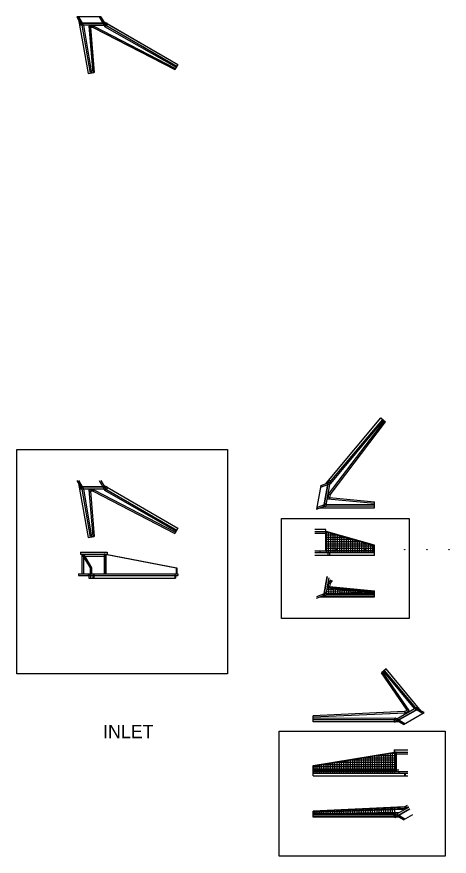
# Model space of a CAD drawing. Extents: x -21 to 491, y -228 to 155.
# Drawn here: x 295.5 to 490.7, y -228.4 to 150.5 of the extents above; entities that cross this region are included whole.
import ezdxf

# ---------------------------------------------------------------- set-up
doc = ezdxf.new("R2010")
doc.units = 0
for name, color, linetype in [('1', 7, 'Continuous'), ('4', 7, 'Continuous'), ('B-Gen-Construction Line', 7, 'Continuous'), ('B-Gen-Hidden', 7, 'Continuous'), ('B-Gen-Object', 7, 'Continuous'), ('B-Gen-Rebar', 7, 'Continuous')]:
    doc.layers.add(name, color=color, linetype=linetype)

msp = doc.modelspace()

# ---------------------------------------------------------------- linework, layer by layer
at = {"layer": '4'}
msp.add_line((429.19, -189.4), (467.92, -189.4), dxfattribs=at)
for points in [[(295.48, -44.74), (390.59, -44.74), (390.59, -146.09), (295.48, -146.09)], [(415, -75.9), (472.51, -75.9), (472.51, -121.1), (415, -121.1)], [(413.88, -171.92), (488.79, -171.92), (488.79, -228.35), (413.88, -228.35)]]:
    msp.add_lwpolyline(points, close=True, dxfattribs=at)
at = {"layer": 'B-Gen-Construction Line'}
for points in [[(323.39, 149.19), (327.69, 124.82), (330.4, 125.3), (328.75, 145.66), (328.75, 146.66), (324.85, 146.66)], [(334.63, 148.39), (368.17, 129.03), (366.8, 126.64), (330.03, 145.66), (330.03, 146.66), (335.63, 146.66)], [(328.75, 146.66), (330.03, 146.66), (330.03, 145.66), (328.75, 145.66)]]:
    msp.add_lwpolyline(points, close=True, dxfattribs=at)
at = {"layer": 'B-Gen-Hidden'}
for p, q in [((323.41, 150.49), (325.49, 146.89)), ((332.65, 150.49), (334.86, 146.66)), ((324.28, 147.66), (324.85, 146.66)), ((325.53, 146.66), (325.49, 146.89)), ((330.19, 146.33), (328.03, 146.33)), ((328.03, 146.33), (329.74, 125.18)), ((328.75, 145.66), (328.09, 145.61)), ((330.03, 145.66), (330.19, 146.33)), ((330.19, 146.33), (367.13, 127.22)), ((335.05, 147.66), (335.63, 146.66)), ((335.9, 147.66), (336.21, 147.48)), ((436.23, -64.98), (461.46, -31.91)), ((323.41, -58.82), (325.49, -62.42)), ((332.65, -58.82), (334.86, -62.65)), ((432.56, -61.83), (436.72, -60.32)), ((435.77, -59.96), (436.85, -59.56)), ((435.91, -59.12), (436.15, -58.85)), ((324.28, -61.65), (324.85, -62.65)), ((325.53, -62.65), (325.49, -62.42)), ((330.19, -62.99), (328.03, -62.99)), ((328.03, -62.99), (329.74, -84.13)), ((328.75, -63.65), (328.09, -63.71)), ((330.03, -63.65), (330.19, -62.99)), ((330.19, -62.99), (367.13, -82.09)), ((335.05, -61.65), (335.63, -62.65)), ((335.9, -61.65), (336.21, -61.83)), ((436.23, -64.98), (435.86, -67.1)), ((435.86, -67.1), (456.98, -69.09)), ((436.86, -65.25), (436.23, -64.98)), ((436.64, -66.51), (436.58, -67.17)), ((430.96, -70.93), (434.86, -69.51)), ((433.89, -70.57), (434.98, -70.18)), ((435.1, -69.51), (434.86, -69.51)), ((434.98, -82.71), (429.94, -82.71)), ((434.86, -81.92), (434.86, -90.71)), ((432.23, -90.71), (429.94, -90.71)), ((324.85, -92.09), (335.85, -92.09)), ((325.53, -92.05), (325.53, -100.88)), ((325.53, -92.88), (326.02, -92.88)), ((335.63, -92.05), (335.63, -100.88)), ((436.64, -91.46), (436.64, -92.71)), ((328.03, -100.88), (328.03, -101.63)), ((328.75, -100.88), (328.75, -101.63)), ((328.75, -101.63), (328.75, -102.88)), ((329.74, -101.63), (366.8, -101.63)), ((330.03, -100.88), (330.03, -101.63)), ((330.03, -100.88), (330.03, -102.88)), ((330.19, -100.88), (330.19, -102.88)), ((436.23, -105.12), (435.86, -107.25)), ((436.23, -105.12), (437.42, -103.57)), ((436.86, -105.39), (436.23, -105.12)), ((430.96, -111.07), (434.86, -109.65)), ((435.1, -109.65), (434.86, -109.65)), ((435.86, -107.25), (456.98, -109.24)), ((436.64, -106.65), (436.58, -107.32)), ((433.89, -110.71), (434.98, -110.32)), ((472.6, -162.66), (460.55, -145.2)), ((470.73, -163.74), (472.6, -162.66)), ((471.65, -162.44), (472.19, -162.06)), ((474.94, -161.7), (475.09, -161.88)), ((478.68, -163.95), (475.09, -161.88)), ((476.52, -161.94), (475.52, -161.36)), ((470.73, -163.74), (429.19, -165.67)), ((470.68, -168.57), (466.86, -166.36)), ((470.54, -163.08), (470.73, -163.74)), ((466.46, -167.75), (466.09, -167.75)), ((467.19, -167.33), (466.19, -166.75)), ((465.94, -181.36), (466.19, -181.31)), ((466.19, -181.36), (466.19, -181.31)), ((466.19, -181.31), (466.78, -181.31)), ((466.31, -181.56), (466.31, -181.31)), ((466.31, -181.56), (466.31, -190.15)), ((466.78, -181.56), (466.78, -181.31)), ((466.78, -181.56), (466.78, -190.15)), ((466.19, -182.15), (472, -182.15)), ((467.92, -190.15), (472, -190.15)), ((470.54, -190.94), (470.54, -192.15)), ((470.73, -206.75), (429.19, -208.67)), ((470.54, -206.09), (470.73, -206.75)), ((470.73, -206.75), (472.22, -205.89)), ((466.46, -210.75), (466.09, -210.75)), ((467.19, -210.33), (466.19, -209.75)), ((470.68, -211.58), (466.86, -209.37))]:
    msp.add_line(p, q, dxfattribs=at)
at = {"layer": 'B-Gen-Object'}
for p, q in [((333.42, 150.49), (322.64, 150.49)), ((322.64, 150.49), (324.28, 147.66)), ((323.39, 149.19), (327.69, 124.82)), ((333.42, 150.49), (335.05, 147.66)), ((334.63, 148.39), (335.9, 147.66)), ((336.21, 147.66), (324.27, 147.66)), ((324.27, 146.66), (324.27, 147.66)), ((336.21, 147.49), (324.27, 147.49)), ((336.21, 146.66), (324.27, 146.66)), ((324.85, 146.66), (328.67, 124.99)), ((325.53, 146.66), (324.87, 146.54)), ((325.53, 146.66), (329.17, 125.08)), ((330.03, 145.66), (328.75, 145.66)), ((328.75, 145.66), (330.4, 125.3)), ((330.03, 145.66), (366.8, 126.64)), ((334.86, 146.66), (335.14, 146.17)), ((335.14, 146.17), (367.42, 127.73)), ((335.63, 146.66), (335.3, 146.08)), ((335.63, 146.66), (367.67, 128.16)), ((336.21, 146.66), (336.21, 147.66)), ((336.21, 147.48), (368.17, 129.03)), ((368.17, 129.03), (366.8, 126.64)), ((327.69, 124.82), (330.4, 125.3)), ((436.15, -58.85), (459.87, -30.58)), ((436.85, -59.56), (460.63, -31.22)), ((436.86, -65.25), (461.97, -32.34)), ((437.25, -60.13), (461.02, -31.54)), ((459.87, -30.58), (461.97, -32.34)), ((322.64, -58.82), (324.28, -61.65)), ((323.39, -60.12), (327.69, -84.49)), ((333.42, -58.82), (335.05, -61.65)), ((432.7, -61.07), (435.77, -59.96)), ((435.97, -58.81), (433.89, -70.58)), ((436.13, -58.84), (434.06, -70.6)), ((436.95, -58.99), (434.88, -70.75)), ((434.97, -60.25), (435.91, -59.12)), ((436.95, -58.99), (435.97, -58.81)), ((436.72, -60.32), (437.25, -60.13)), ((436.85, -59.56), (437.36, -59.99)), ((336.21, -61.65), (324.27, -61.65)), ((324.27, -62.65), (324.27, -61.65)), ((336.21, -61.82), (324.27, -61.82)), ((336.21, -62.65), (324.27, -62.65)), ((324.85, -62.65), (328.67, -84.32)), ((325.53, -62.65), (324.87, -62.77)), ((325.53, -62.65), (329.17, -84.23)), ((330.03, -63.65), (328.75, -63.65)), ((328.75, -63.65), (330.4, -84.01)), ((330.03, -63.65), (366.8, -82.67)), ((334.63, -60.92), (335.9, -61.65)), ((334.86, -62.65), (335.14, -63.14)), ((335.14, -63.14), (367.42, -81.59)), ((335.63, -62.65), (335.3, -63.23)), ((335.63, -62.65), (367.67, -81.15)), ((336.21, -62.65), (336.21, -61.65)), ((336.21, -61.83), (368.17, -80.29)), ((432.7, -61.07), (430.83, -71.69)), ((436.86, -65.25), (436.64, -66.51)), ((436.64, -66.51), (456.98, -68.43)), ((430.83, -71.69), (433.89, -70.57)), ((432.23, -71.18), (456.98, -71.18)), ((434.88, -70.75), (433.89, -70.58)), ((434.98, -70.18), (456.98, -70.18)), ((435.1, -69.51), (456.98, -69.68)), ((456.98, -71.18), (456.98, -68.43)), ((368.17, -80.29), (366.8, -82.67)), ((434.98, -80.92), (429.94, -80.92)), ((434.98, -81.92), (429.94, -81.92)), ((434.98, -81.92), (429.94, -81.92)), ((434.98, -90.71), (434.98, -80.92)), ((435.1, -81.88), (434.98, -81.88)), ((456.98, -88.05), (435.1, -81.88)), ((327.69, -84.49), (330.4, -84.01)), ((456.98, -90.71), (432.23, -90.71)), ((432.23, -90.71), (432.23, -91.5)), ((456.98, -92.71), (456.98, -88.05)), ((324.27, -91.09), (336.21, -91.09)), ((324.27, -91.09), (324.27, -92.09)), ((324.27, -92.09), (324.85, -92.09)), ((324.85, -92.05), (325.53, -92.05)), ((324.85, -92.05), (328.67, -98.22)), ((324.85, -92.05), (324.85, -100.88)), ((325.53, -92.05), (329.17, -98.22)), ((326.02, -92.88), (334.86, -92.88)), ((334.86, -92.05), (334.86, -100.88)), ((335.21, -92.05), (334.86, -92.05)), ((335.14, -92.05), (335.14, -100.88)), ((335.21, -92.05), (335.63, -92.05)), ((335.3, -92.05), (367.42, -98.22)), ((335.63, -92.05), (367.67, -98.22)), ((335.85, -92.09), (336.21, -92.09)), ((336.21, -91.09), (336.21, -92.09)), ((432.23, -91.5), (429.94, -91.5)), ((456.98, -92.71), (429.94, -92.71)), ((436.75, -91.46), (432.23, -91.46)), ((435.86, -91.46), (435.86, -92.71)), ((456.98, -91.46), (436.75, -91.46)), ((328.67, -98.22), (329.17, -98.22)), ((328.67, -98.22), (328.67, -100.88)), ((329.17, -98.22), (329.17, -100.88)), ((367.42, -98.22), (367.42, -100.88)), ((367.42, -98.22), (367.67, -98.22)), ((367.67, -98.22), (367.67, -100.88)), ((323.39, -100.88), (323.39, -101.63)), ((323.39, -100.88), (368.17, -100.88)), ((323.39, -101.63), (329.74, -101.63)), ((327.69, -100.88), (327.69, -101.63)), ((328.03, -101.63), (328.03, -102.88)), ((329.74, -101.63), (329.74, -102.88)), ((330.4, -102.88), (330.4, -100.88)), ((366.8, -100.88), (366.8, -102.88)), ((366.8, -101.63), (368.17, -101.63)), ((367.13, -101.63), (367.13, -102.88)), ((368.17, -100.88), (368.17, -101.63)), ((435.42, -102.05), (433.89, -110.72)), ((435.57, -102.16), (434.06, -110.75)), ((328.03, -102.88), (366.8, -102.88)), ((329.74, -102.88), (330.4, -102.88)), ((329.74, -102.88), (330.4, -102.88)), ((366.8, -102.88), (367.13, -102.88)), ((436.32, -102.73), (434.88, -110.89)), ((436.86, -105.39), (436.64, -106.65)), ((436.86, -105.39), (437.95, -103.97)), ((435.1, -109.65), (456.98, -109.82)), ((436.64, -106.65), (456.98, -108.57)), ((456.98, -111.32), (456.98, -108.57)), ((430.83, -111.83), (433.89, -110.71)), ((432.23, -111.32), (456.98, -111.32)), ((434.88, -110.89), (433.89, -110.72)), ((434.98, -110.32), (456.98, -110.32)), ((462.15, -143.86), (460.04, -145.63)), ((478.05, -162.82), (462.15, -143.86)), ((471.65, -162.44), (460.04, -145.63)), ((474.94, -161.7), (461, -144.83)), ((475.52, -161.36), (461.38, -144.51)), ((465.68, -167.04), (476.03, -161.07)), ((466.1, -167.76), (476.44, -161.79)), ((466.18, -167.91), (476.53, -161.93)), ((470.54, -163.08), (471.65, -162.44)), ((476.03, -161.07), (476.53, -161.93)), ((479.35, -163.57), (476.52, -161.94)), ((470.54, -163.08), (429.19, -165)), ((429.19, -167.75), (429.19, -165)), ((466.37, -166.08), (429.19, -166.25)), ((466.19, -166.75), (466.19, -166.08)), ((466.86, -166.36), (466.37, -166.08)), ((470.02, -168.96), (479.35, -163.57)), ((466.19, -166.75), (429.19, -166.75)), ((466.09, -167.75), (429.19, -167.75)), ((465.68, -167.04), (466.18, -167.91)), ((467.92, -167.75), (466.46, -167.75)), ((470.02, -168.96), (467.19, -167.33)), ((429.19, -187.48), (465.94, -181.36)), ((465.74, -180.36), (472, -180.36)), ((465.74, -180.36), (465.74, -181.36)), ((465.74, -181.36), (472, -181.36)), ((466.19, -181.36), (466.19, -190.15)), ((429.19, -192.15), (429.19, -187.48)), ((429.19, -190.15), (467.92, -190.15)), ((429.19, -190.9), (467.92, -190.9)), ((429.19, -192.15), (472, -192.15)), ((467.92, -190.15), (467.92, -190.94)), ((467.92, -190.9), (467.92, -190.9)), ((467.92, -190.94), (472, -190.94)), ((470.73, -190.94), (470.73, -192.15)), ((470.54, -206.09), (429.19, -208)), ((429.19, -210.75), (429.19, -208)), ((465.68, -210.05), (472.39, -206.18)), ((466.1, -210.77), (472.81, -206.9)), ((466.18, -210.91), (472.89, -207.04)), ((470.54, -206.09), (471.89, -205.31)), ((466.37, -209.09), (429.19, -209.25)), ((466.19, -209.75), (429.19, -209.75)), ((466.09, -210.75), (429.19, -210.75)), ((465.68, -210.05), (466.18, -210.91)), ((466.19, -209.75), (466.19, -209.09)), ((466.86, -209.37), (466.37, -209.09)), ((467.92, -210.75), (466.46, -210.75)), ((470.02, -211.96), (467.19, -210.33)), ((470.02, -211.96), (474.3, -209.49))]:
    msp.add_line(p, q, dxfattribs=at)
for centre, radius in [((439.73, -89.96), 0.0834), ((452.73, -89.96), 0.0834), ((470.58, -89.96), 0.0834), ((480.58, -89.96), 0.0834), ((490.58, -89.96), 0.0834), ((437.44, -189.4), 0.0833), ((447.44, -189.4), 0.0833), ((457.44, -189.4), 0.0833)]:
    msp.add_circle(centre, radius, dxfattribs=at)
at = {"layer": 'B-Gen-Rebar'}
for p, q in [((456.81, -88.26), (435.15, -82.15)), ((436.55, -82.46), (435.15, -82.46)), ((435.23, -91.3), (435.23, -82.14)), ((436.23, -91.3), (436.23, -82.37)), ((437.23, -91.3), (437.23, -82.65)), ((438.23, -91.3), (438.23, -82.93)), ((439.23, -91.3), (439.23, -83.22)), ((440.1, -83.46), (435.15, -83.46)), ((443.65, -84.46), (435.15, -84.46)), ((447.2, -85.46), (435.15, -85.46)), ((450.75, -86.46), (435.15, -86.46)), ((440.23, -91.3), (440.23, -83.5)), ((441.23, -91.3), (441.23, -83.78)), ((442.23, -91.3), (442.23, -84.06)), ((443.23, -91.3), (443.23, -84.34)), ((444.23, -91.3), (444.23, -84.63)), ((445.23, -91.3), (445.23, -84.91)), ((446.23, -91.3), (446.23, -85.19)), ((447.23, -91.3), (447.23, -85.47)), ((448.23, -91.3), (448.23, -85.75)), ((449.23, -91.3), (449.23, -86.03)), ((450.23, -91.3), (450.23, -86.32)), ((451.23, -91.3), (451.23, -86.6)), ((452.23, -91.3), (452.23, -86.88)), ((454.3, -87.46), (435.15, -87.46)), ((456.81, -88.46), (435.15, -88.46)), ((456.81, -89.46), (435.15, -89.46)), ((456.81, -90.46), (435.15, -90.46)), ((453.23, -91.3), (453.23, -87.16)), ((454.23, -91.3), (454.23, -87.44)), ((455.23, -91.3), (455.23, -87.73)), ((456.23, -91.3), (456.23, -88.01)), ((456.73, -91.3), (456.73, -88.15)), ((435.73, -108.98), (435.38, -108.98)), ((435.58, -107.89), (456.81, -109.22)), ((456.81, -109.65), (435.73, -108.98)), ((435.77, -106.82), (456.81, -108.8)), ((436.23, -106.78), (436.23, -110.15)), ((437.23, -106.87), (437.23, -110.15)), ((438.23, -106.97), (438.23, -110.15)), ((439.23, -107.06), (439.23, -110.15)), ((440.23, -107.16), (440.23, -110.15)), ((441.23, -107.25), (441.23, -110.15)), ((442.23, -107.35), (442.23, -110.15)), ((443.23, -107.44), (443.23, -110.15)), ((444.23, -107.53), (444.23, -110.15)), ((445.23, -107.63), (445.23, -110.15)), ((446.23, -107.72), (446.23, -110.15)), ((447.23, -107.82), (447.23, -110.15)), ((448.23, -107.91), (448.23, -110.15)), ((449.23, -108.01), (449.23, -110.15)), ((450.23, -108.1), (450.23, -110.15)), ((451.23, -108.19), (451.23, -110.15)), ((452.23, -108.29), (452.23, -110.15)), ((453.23, -108.38), (453.23, -110.15)), ((454.23, -108.48), (454.23, -110.15)), ((455.23, -108.57), (455.23, -110.15)), ((456.23, -108.66), (456.23, -110.15)), ((456.73, -108.71), (456.73, -110.15)), ((433.41, -111.07), (456.81, -111.07)), ((435.19, -110.07), (456.81, -110.07)), ((429.36, -187.71), (466.02, -181.6)), ((464.94, -181.69), (464.94, -190.73)), ((465.94, -181.56), (465.94, -190.73)), ((441.94, -185.53), (441.94, -190.73)), ((442.94, -185.36), (442.94, -190.73)), ((443.94, -185.19), (443.94, -190.73)), ((444.94, -185.03), (444.94, -190.73)), ((445.7, -184.9), (466.02, -184.9)), ((445.94, -184.86), (445.94, -190.73)), ((446.94, -184.69), (446.94, -190.73)), ((447.94, -184.53), (447.94, -190.73)), ((448.94, -184.36), (448.94, -190.73)), ((449.94, -184.19), (449.94, -190.73)), ((450.94, -184.03), (450.94, -190.73)), ((451.7, -183.9), (466.02, -183.9)), ((451.94, -183.86), (451.94, -190.73)), ((452.94, -183.69), (452.94, -190.73)), ((453.94, -183.53), (453.94, -190.73)), ((454.94, -183.36), (454.94, -190.73)), ((455.94, -183.19), (455.94, -190.73)), ((456.94, -183.03), (456.94, -190.73)), ((457.7, -182.9), (466.02, -182.9)), ((457.94, -182.86), (457.94, -190.73)), ((458.94, -182.69), (458.94, -190.73)), ((459.94, -182.53), (459.94, -190.73)), ((460.94, -182.36), (460.94, -190.73)), ((461.94, -182.19), (461.94, -190.73)), ((462.94, -182.03), (462.94, -190.73)), ((463.7, -181.9), (466.02, -181.9)), ((463.94, -181.86), (463.94, -190.73)), ((429.36, -187.9), (466.02, -187.9)), ((429.36, -188.9), (466.02, -188.9)), ((429.44, -190.73), (429.44, -187.57)), ((429.94, -187.53), (429.94, -190.73)), ((430.94, -187.36), (430.94, -190.73)), ((431.94, -187.19), (431.94, -190.73)), ((432.94, -187.03), (432.94, -190.73)), ((433.7, -186.9), (466.02, -186.9)), ((433.94, -186.86), (433.94, -190.73)), ((434.94, -186.69), (434.94, -190.73)), ((435.94, -186.53), (435.94, -190.73)), ((436.94, -186.36), (436.94, -190.73)), ((437.94, -186.19), (437.94, -190.73)), ((438.94, -186.03), (438.94, -190.73)), ((439.7, -185.9), (466.02, -185.9)), ((439.94, -185.86), (439.94, -190.73)), ((440.94, -185.69), (440.94, -190.73)), ((429.36, -189.9), (466.02, -189.9)), ((472.02, -206.19), (429.36, -208.24)), ((470.08, -207.32), (429.36, -208.66)), ((429.44, -208.16), (429.44, -209.59)), ((429.94, -208.14), (429.94, -209.59)), ((430.94, -208.09), (430.94, -209.59)), ((431.94, -208.04), (431.94, -209.59)), ((432.94, -208), (432.94, -209.59)), ((433.94, -207.95), (433.94, -209.59)), ((434.94, -207.9), (434.94, -209.59)), ((435.94, -207.86), (435.94, -209.59)), ((436.94, -207.81), (436.94, -209.59)), ((437.94, -207.77), (437.94, -209.59)), ((438.94, -207.72), (438.94, -209.59)), ((439.94, -207.67), (439.94, -209.59)), ((440.94, -207.63), (440.94, -209.59)), ((441.94, -207.58), (441.94, -209.59)), ((442.94, -207.53), (442.94, -209.59)), ((443.94, -207.49), (443.94, -209.59)), ((444.94, -207.44), (444.94, -209.59)), ((445.94, -207.39), (445.94, -209.59)), ((446.94, -207.35), (446.94, -209.59)), ((447.94, -207.3), (447.94, -209.59)), ((448.94, -207.26), (448.94, -209.59)), ((449.94, -207.21), (449.94, -209.59)), ((450.94, -207.16), (450.94, -209.59)), ((451.94, -207.12), (451.94, -209.59)), ((452.94, -207.07), (452.94, -209.59)), ((453.94, -207.02), (453.94, -209.59)), ((454.94, -206.98), (454.94, -209.59)), ((455.94, -206.93), (455.94, -209.59)), ((456.94, -206.88), (456.94, -209.59)), ((457.94, -206.84), (457.94, -209.59)), ((458.94, -206.79), (458.94, -209.59)), ((459.94, -206.75), (459.94, -209.59)), ((460.94, -206.7), (460.94, -209.59)), ((461.94, -206.65), (461.94, -209.59)), ((462.94, -206.61), (462.94, -209.59)), ((463.94, -206.56), (463.94, -209.59)), ((464.94, -206.51), (464.94, -209.59)), ((465.94, -206.47), (465.94, -209.59)), ((429.36, -209.08), (468.17, -208.42)), ((466.29, -209.5), (429.36, -209.5)), ((467.16, -210.5), (429.36, -210.5))]:
    msp.add_line(p, q, dxfattribs=at)

# ---------------------------------------------------------------- texts
at = {"layer": '1'}
msp.add_text('INLET', height=6, dxfattribs=at).set_placement((334.44, -175.1))

doc.saveas('drawing.dxf')
